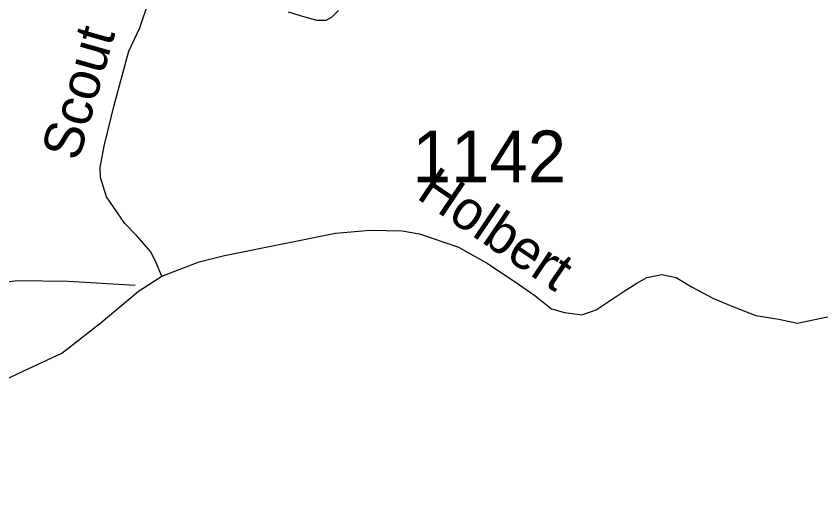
# Model space of a CAD drawing. Extents: x 990631 to 1056237, y 535999 to 585651.
# Drawn here: x 1010994 to 1012942, y 562348 to 563508 of the extents above; entities that cross this region are included whole.
import ezdxf

# ---------------------------------------------------------------- set-up
doc = ezdxf.new("R2010")
doc.units = 0
for name, color, linetype in [('Exist Road Non-System Type 51', 7, 'Continuous'), ('Exist Road Secondary Type 41 Attributed', 7, 'Continuous'), ('Exist Road Secondary Type 51 Attributed', 7, 'Continuous'), ('Exist Road Secondary Type 51 Label', 7, 'Continuous'), ('Exist Road Secondary Type 51 Number Label', 7, 'Continuous')]:
    doc.layers.add(name, color=color, linetype=linetype)

msp = doc.modelspace()

# ---------------------------------------------------------------- linework, layer by layer
at = {"layer": 'Exist Road Non-System Type 51'}
msp.add_lwpolyline([(1011281.6, 562856.8), (1011119.7, 562866), (1010997.7, 562868.3), (1010822.9, 562848)], dxfattribs=at)
at = {"layer": 'Exist Road Secondary Type 41 Attributed'}
for points in [[(1011346, 562879), (1011332.7, 562911.4), (1011319.8, 562938.1), (1011286.1, 562976.7), (1011256.4, 563006.5), (1011212.7, 563071.2), (1011198.2, 563117.7), (1011196.9, 563141.8), (1011206.7, 563193.4), (1011230.7, 563292.7), (1011266.4, 563423.7), (1011293, 563480), (1011314.8, 563544.3)], [(1011652.5, 563518.6), (1011689.2, 563507.2), (1011721.2, 563498.5), (1011744.3, 563498.9), (1011758.7, 563506.4), (1011774.4, 563522.1)]]:
    msp.add_lwpolyline(points, dxfattribs=at)
at = {"layer": 'Exist Road Secondary Type 51 Attributed'}
for points in [[(1011346, 562879), (1011436.6, 562913.7), (1011498.1, 562929.6), (1011767.1, 562983.2), (1011850.7, 562990.4), (1011928.4, 562989.2), (1011970.1, 562981.7), (1012064.2, 562949.6), (1012132.2, 562911.5), (1012201.6, 562865.2), (1012249.2, 562832.5), (1012289.3, 562800.5), (1012321, 562791.4), (1012363.3, 562785.4), (1012398, 562797.5), (1012462.9, 562841.2), (1012496.1, 562862.4), (1012520.2, 562876), (1012556.5, 562883.5), (1012591.2, 562876), (1012628.9, 562853.3), (1012680.2, 562826.1), (1012730, 562805), (1012784.4, 562783.9), (1012840.2, 562774.8), (1012885.6, 562765.2), (1012965.5, 562782.4)], [(1009803.1, 562286.2), (1009871.1, 562284.9), (1009981.9, 562292.4), (1010234.9, 562306), (1010438.9, 562319.6), (1010489.9, 562337.9), (1010537.5, 562361.1), (1010639.6, 562430.4), (1010730.2, 562493.8), (1010801.2, 562545.3), (1010897.8, 562595.1), (1011000.4, 562644.9), (1011104.5, 562693.3), (1011199.6, 562767.2), (1011290.2, 562842.8), (1011346, 562879)]]:
    msp.add_lwpolyline(points, dxfattribs=at)

# ---------------------------------------------------------------- texts
at = {"layer": 'Exist Road Secondary Type 51 Label'}
for s, rotation, p in [('Scout', 74.0888, (1011144.6, 563155)), ('Scout', 74.0888, (1011144.6, 563155)), ('Holbert', 325.9627, (1011959.8, 563069.2)), ('Holbert', 325.9627, (1011959.8, 563069.2))]:
    msp.add_text(s, height=95, rotation=rotation, dxfattribs=at).set_placement(p)
at = {"layer": 'Exist Road Secondary Type 51 Number Label'}
msp.add_text('1142', height=125, dxfattribs=at).set_placement((1011953.2, 563106.6))

doc.saveas('drawing.dxf')
